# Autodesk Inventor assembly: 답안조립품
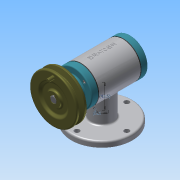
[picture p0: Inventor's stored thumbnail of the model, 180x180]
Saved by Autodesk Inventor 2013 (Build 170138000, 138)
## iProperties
Created: 2018-11
Part Number: 답안조립품
Document SubType Name: Assembly
Designer: Administrator
Mass: 1873.16 g
Surface Area: 1425.69 cm^2
Volume: 459.811 cm^3
Density: 4.07377 g/cm^3
Author: Administrator
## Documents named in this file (18)
- C:\Users\Administrator\Desktop\381107V1002\답안조립품.iam
- C:\Users\Administrator\Desktop\381107V1002\본체.ipt
- C:\Users\Administrator\Desktop\381107V1002\V-벨트풀리.ipt
- C:\Users\Administrator\Desktop\381107V1002\가변스프링.ipt
- C:\Users\Administrator\Desktop\381107V1002\개스킷.ipt
- C:\Users\Administrator\Desktop\381107V1002\뒤커버.ipt
- C:\Users\Administrator\Desktop\381107V1002\멈춤나사 M3x8.ipt
- C:\Users\Administrator\Desktop\381107V1002\베어링 6201.ipt
- C:\Users\Administrator\Desktop\381107V1002\베어링 6202.ipt
- C:\Users\Administrator\Desktop\381107V1002\본체커버.ipt
- C:\Users\Administrator\Desktop\381107V1002\볼트 M3x0.5x8.ipt
- C:\Users\Administrator\Desktop\381107V1002\슬라이드.ipt
- C:\Users\Administrator\Desktop\381107V1002\앞커버.ipt
- C:\Users\Administrator\Desktop\381107V1002\오일 실 12 22 7.ipt
- 오일 실 12 22 7.ipt
- C:\Users\Administrator\Desktop\381107V1002\키 4x4x18.ipt
- 키 4x4x18.ipt
- C:\Users\Administrator\Desktop\381107V1002\편심축.ipt
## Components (4 placed, 3 different names)
1. V-벨트풀리:1
2. 가변스프링:1
3. 개스킷:1
4. 개스킷:2
